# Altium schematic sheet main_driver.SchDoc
size A3
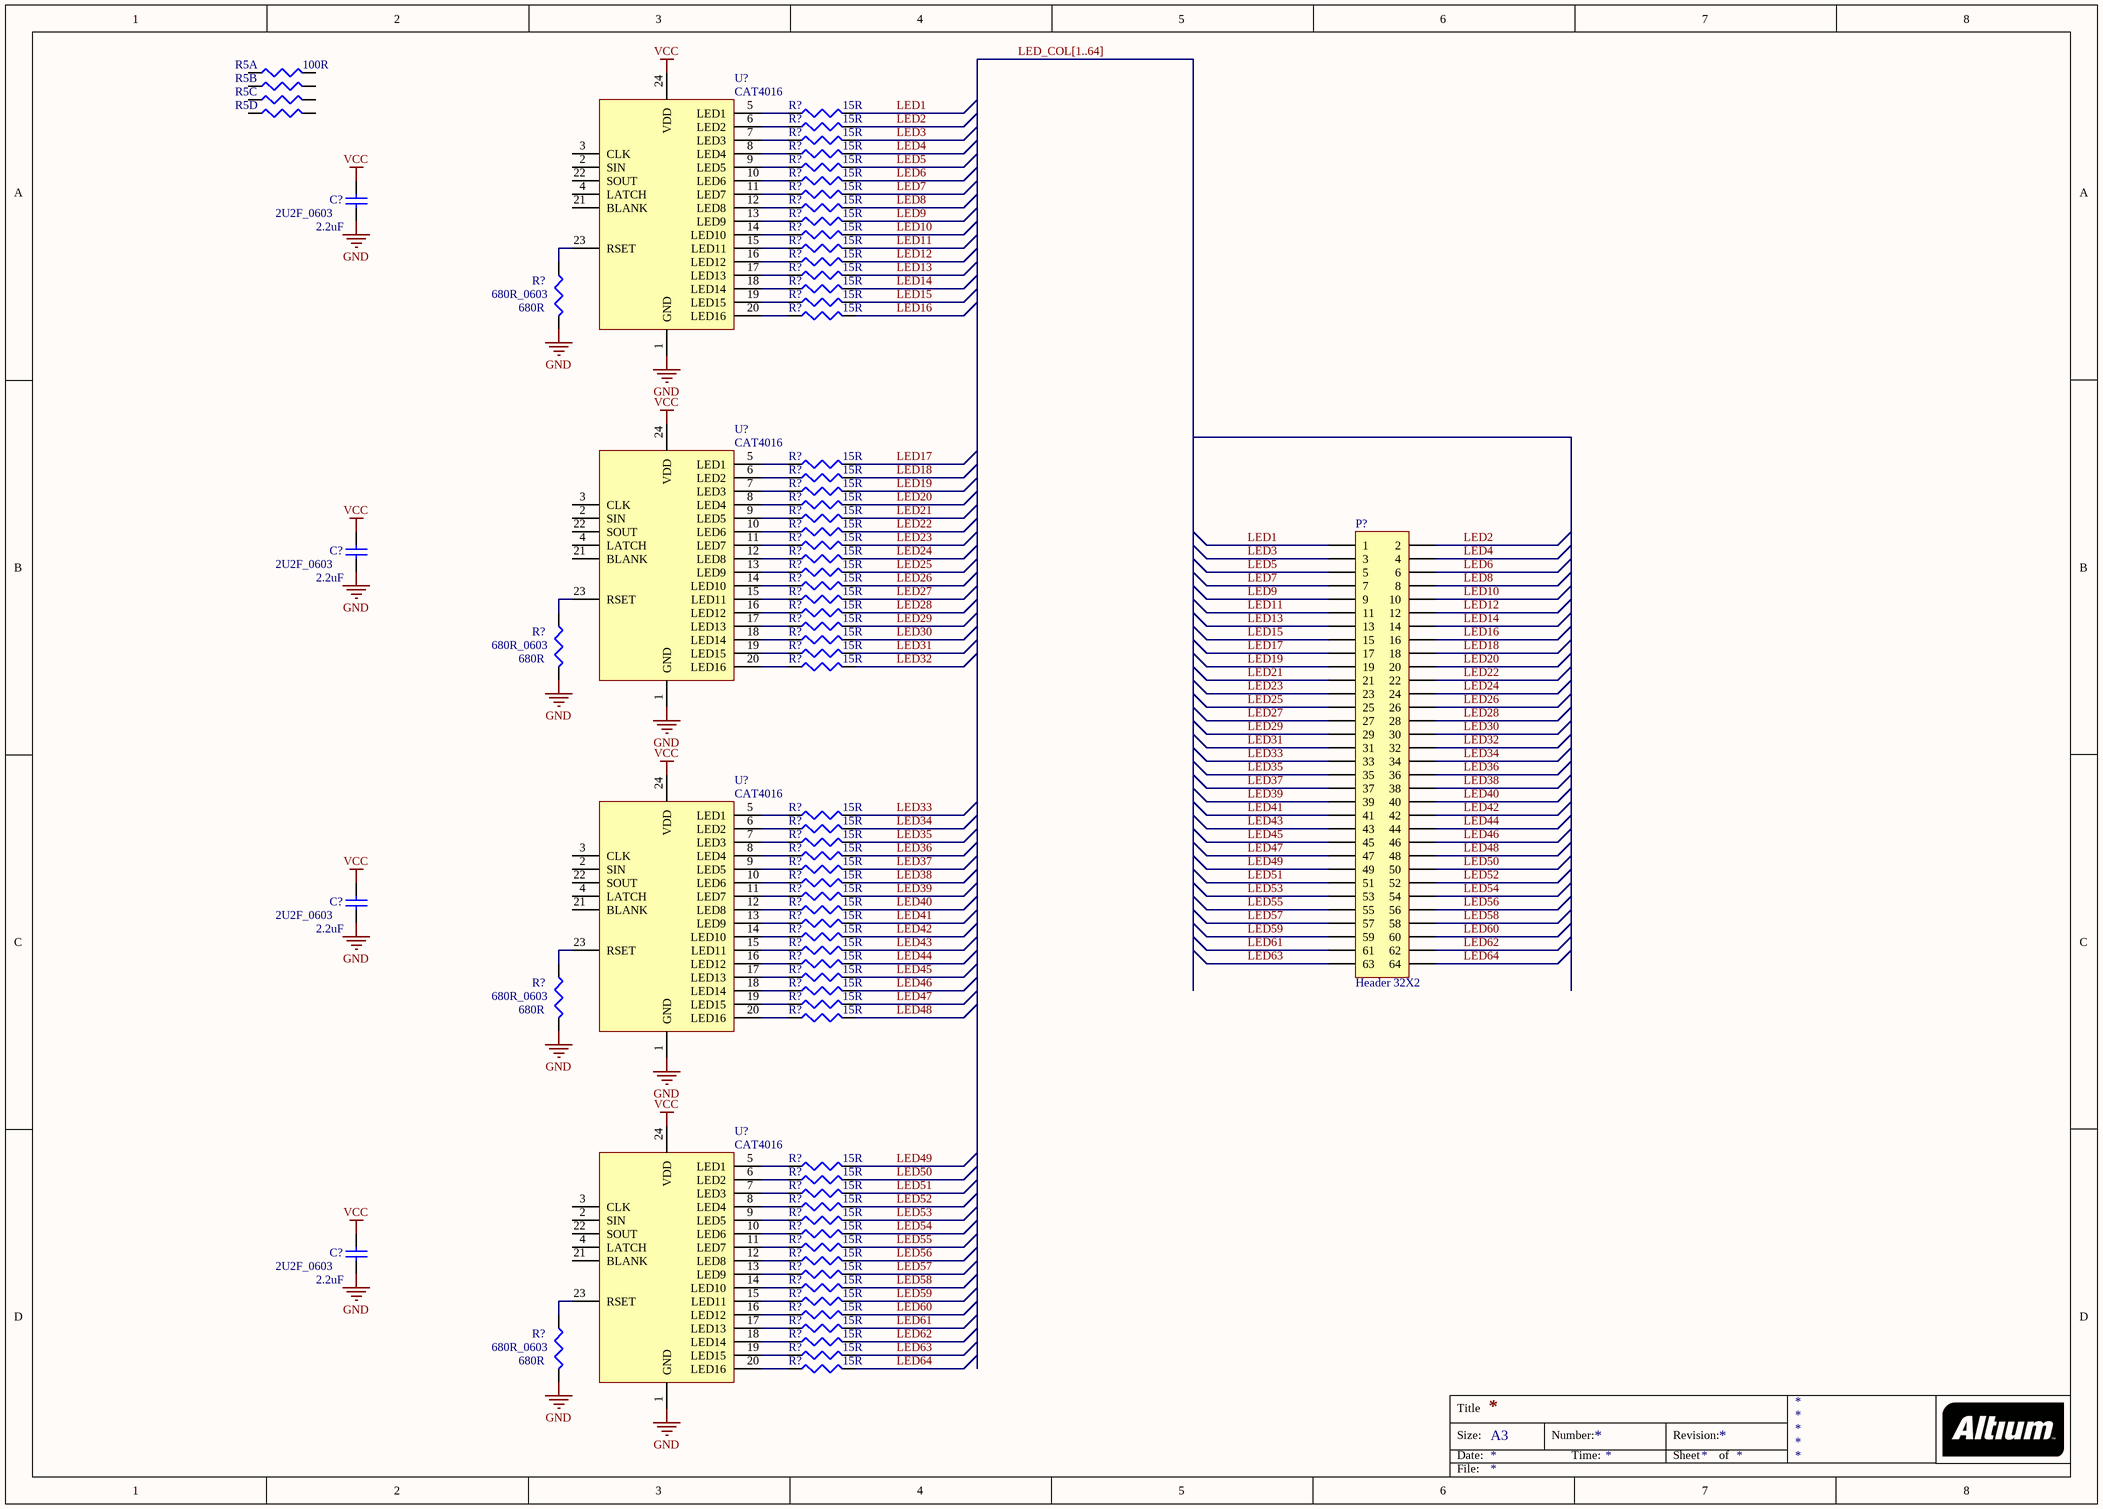
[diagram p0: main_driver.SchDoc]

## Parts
(Parts that share a designator on the sheet are numbered #1, #2 ... from top to bottom, then left to right.)
C?#1  2U2F_0603  value 2.2uF  [C0603]
C?#2  2U2F_0603  value 2.2uF  [C0603]
C?#3  2U2F_0603  value 2.2uF  [C0603]
C?#4  2U2F_0603  value 2.2uF  [C0603]
P?  Header 32X2  [HDR2X32_1MM]
R5  value 100R  [BCN16]  (hidden comment: Res_Array_BCN16)  (parts A,B,C,D of 4)
R?#1  value 15R  [R1206]  (hidden comment: 15R_1206)
R?#2  value 15R  [R1206]  (hidden comment: 15R_1206)
R?#3  value 15R  [R1206]  (hidden comment: 15R_1206)
R?#4  value 15R  [R1206]  (hidden comment: 15R_1206)
R?#5  value 15R  [R1206]  (hidden comment: 15R_1206)
R?#6  value 15R  [R1206]  (hidden comment: 15R_1206)
R?#7  value 15R  [R1206]  (hidden comment: 15R_1206)
R?#8  value 15R  [R1206]  (hidden comment: 15R_1206)
R?#9  value 15R  [R1206]  (hidden comment: 15R_1206)
R?#10  value 15R  [R1206]  (hidden comment: 15R_1206)
R?#11  value 15R  [R1206]  (hidden comment: 15R_1206)
R?#12  value 15R  [R1206]  (hidden comment: 15R_1206)
R?#13  value 15R  [R1206]  (hidden comment: 15R_1206)
R?#14  680R_0603  value 680R  [R0603]
R?#15  value 15R  [R1206]  (hidden comment: 15R_1206)
R?#16  value 15R  [R1206]  (hidden comment: 15R_1206)
R?#17  value 15R  [R1206]  (hidden comment: 15R_1206)
R?#18  value 15R  [R1206]  (hidden comment: 15R_1206)
R?#19  value 15R  [R1206]  (hidden comment: 15R_1206)
R?#20  value 15R  [R1206]  (hidden comment: 15R_1206)
R?#21  value 15R  [R1206]  (hidden comment: 15R_1206)
R?#22  value 15R  [R1206]  (hidden comment: 15R_1206)
R?#23  value 15R  [R1206]  (hidden comment: 15R_1206)
R?#24  value 15R  [R1206]  (hidden comment: 15R_1206)
R?#25  value 15R  [R1206]  (hidden comment: 15R_1206)
R?#26  value 15R  [R1206]  (hidden comment: 15R_1206)
R?#27  value 15R  [R1206]  (hidden comment: 15R_1206)
R?#28  value 15R  [R1206]  (hidden comment: 15R_1206)
R?#29  value 15R  [R1206]  (hidden comment: 15R_1206)
R?#30  value 15R  [R1206]  (hidden comment: 15R_1206)
R?#31  680R_0603  value 680R  [R0603]
R?#32  value 15R  [R1206]  (hidden comment: 15R_1206)
R?#33  value 15R  [R1206]  (hidden comment: 15R_1206)
R?#34  value 15R  [R1206]  (hidden comment: 15R_1206)
R?#35  value 15R  [R1206]  (hidden comment: 15R_1206)
R?#36  value 15R  [R1206]  (hidden comment: 15R_1206)
R?#37  value 15R  [R1206]  (hidden comment: 15R_1206)
R?#38  value 15R  [R1206]  (hidden comment: 15R_1206)
R?#39  value 15R  [R1206]  (hidden comment: 15R_1206)
R?#40  value 15R  [R1206]  (hidden comment: 15R_1206)
R?#41  value 15R  [R1206]  (hidden comment: 15R_1206)
R?#42  value 15R  [R1206]  (hidden comment: 15R_1206)
R?#43  value 15R  [R1206]  (hidden comment: 15R_1206)
R?#44  value 15R  [R1206]  (hidden comment: 15R_1206)
R?#45  value 15R  [R1206]  (hidden comment: 15R_1206)
R?#46  value 15R  [R1206]  (hidden comment: 15R_1206)
R?#47  value 15R  [R1206]  (hidden comment: 15R_1206)
R?#48  680R_0603  value 680R  [R0603]
R?#49  value 15R  [R1206]  (hidden comment: 15R_1206)
R?#50  value 15R  [R1206]  (hidden comment: 15R_1206)
R?#51  value 15R  [R1206]  (hidden comment: 15R_1206)
R?#52  value 15R  [R1206]  (hidden comment: 15R_1206)
R?#53  value 15R  [R1206]  (hidden comment: 15R_1206)
R?#54  value 15R  [R1206]  (hidden comment: 15R_1206)
R?#55  value 15R  [R1206]  (hidden comment: 15R_1206)
R?#56  value 15R  [R1206]  (hidden comment: 15R_1206)
R?#57  value 15R  [R1206]  (hidden comment: 15R_1206)
R?#58  value 15R  [R1206]  (hidden comment: 15R_1206)
R?#59  value 15R  [R1206]  (hidden comment: 15R_1206)
R?#60  value 15R  [R1206]  (hidden comment: 15R_1206)
R?#61  value 15R  [R1206]  (hidden comment: 15R_1206)
R?#62  value 15R  [R1206]  (hidden comment: 15R_1206)
R?#63  value 15R  [R1206]  (hidden comment: 15R_1206)
R?#64  value 15R  [R1206]  (hidden comment: 15R_1206)
R?#65  680R_0603  value 680R  [R0603]
R?#66  value 15R  [R1206]  (hidden comment: 15R_1206)
R?#67  value 15R  [R1206]  (hidden comment: 15R_1206)
R?#68  value 15R  [R1206]  (hidden comment: 15R_1206)
U?#1  CAT4016  [SOIC-24_W]
U?#2  CAT4016  [SOIC-24_W]
U?#3  CAT4016  [SOIC-24_W]
U?#4  CAT4016  [SOIC-24_W]

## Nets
GND: C?#1.1 C?#2.1 C?#3.1 C?#4.1 R?#14.2 R?#31.2 R?#48.2 R?#65.2 U?#1.1(GND) U?#2.1(GND) U?#3.1(GND) U?#4.1(GND)
VCC: C?#1.2 C?#2.2 C?#3.2 C?#4.2 U?#1.24(VDD) U?#2.24(VDD) U?#3.24(VDD) U?#4.24(VDD)
LED1: P?.1 R?#1.2
LED2: P?.2 R?#2.2
LED3: P?.3 R?#3.2
LED4: P?.4 R?#4.2
LED5: P?.5 R?#5.2
LED6: P?.6 R?#6.2
LED7: P?.7 R?#7.2
LED8: P?.8 R?#8.2
LED9: P?.9 R?#9.2
LED10: P?.10 R?#10.2
LED11: P?.11 R?#11.2
LED12: P?.12 R?#12.2
LED13: P?.13 R?#13.2
LED14: P?.14 R?#15.2
LED15: P?.15 R?#16.2
LED16: P?.16 R?#17.2
LED17: P?.17 R?#18.2
LED18: P?.18 R?#19.2
LED19: P?.19 R?#20.2
LED20: P?.20 R?#21.2
LED21: P?.21 R?#22.2
LED22: P?.22 R?#23.2
LED23: P?.23 R?#24.2
LED24: P?.24 R?#25.2
LED25: P?.25 R?#26.2
LED26: P?.26 R?#27.2
LED27: P?.27 R?#28.2
LED28: P?.28 R?#29.2
LED29: P?.29 R?#30.2
LED30: P?.30 R?#32.2
LED31: P?.31 R?#33.2
LED32: P?.32 R?#34.2
LED33: P?.33 R?#35.2
LED34: P?.34 R?#36.2
LED35: P?.35 R?#37.2
LED36: P?.36 R?#38.2
LED37: P?.37 R?#39.2
LED38: P?.38 R?#40.2
LED39: P?.39 R?#41.2
LED40: P?.40 R?#42.2
LED41: P?.41 R?#43.2
LED42: P?.42 R?#44.2
LED43: P?.43 R?#45.2
LED44: P?.44 R?#46.2
LED45: P?.45 R?#47.2
LED46: P?.46 R?#49.2
LED47: P?.47 R?#50.2
LED48: P?.48 R?#51.2
LED49: P?.49 R?#52.2
LED50: P?.50 R?#53.2
LED51: P?.51 R?#54.2
LED52: P?.52 R?#55.2
LED53: P?.53 R?#56.2
LED54: P?.54 R?#57.2
LED55: P?.55 R?#58.2
LED56: P?.56 R?#59.2
LED57: P?.57 R?#60.2
LED58: P?.58 R?#61.2
LED59: P?.59 R?#62.2
LED60: P?.60 R?#63.2
LED61: P?.61 R?#64.2
LED62: P?.62 R?#66.2
LED63: P?.63 R?#67.2
LED64: P?.64 R?#68.2
NetR?#1_1: R?#1.1 U?#1.5(LED1)
NetR?#2_1: R?#2.1 U?#1.6(LED2)
NetR?#3_1: R?#3.1 U?#1.7(LED3)
NetR?#4_1: R?#4.1 U?#1.8(LED4)
NetR?#5_1: R?#5.1 U?#1.9(LED5)
NetR?#6_1: R?#6.1 U?#1.10(LED6)
NetR?#7_1: R?#7.1 U?#1.11(LED7)
NetR?#8_1: R?#8.1 U?#1.12(LED8)
NetR?#9_1: R?#9.1 U?#1.13(LED9)
NetR?#10_1: R?#10.1 U?#1.14(LED10)
NetR?#11_1: R?#11.1 U?#1.15(LED11)
NetR?#12_1: R?#12.1 U?#1.16(LED12)
NetR?#13_1: R?#13.1 U?#1.17(LED13)
NetR?#14_1: R?#14.1 U?#1.23(RSET)
NetR?#15_1: R?#15.1 U?#1.18(LED14)
NetR?#16_1: R?#16.1 U?#1.19(LED15)
NetR?#17_1: R?#17.1 U?#1.20(LED16)
NetR?#18_1: R?#18.1 U?#2.5(LED1)
NetR?#19_1: R?#19.1 U?#2.6(LED2)
NetR?#20_1: R?#20.1 U?#2.7(LED3)
NetR?#21_1: R?#21.1 U?#2.8(LED4)
NetR?#22_1: R?#22.1 U?#2.9(LED5)
NetR?#23_1: R?#23.1 U?#2.10(LED6)
NetR?#24_1: R?#24.1 U?#2.11(LED7)
NetR?#25_1: R?#25.1 U?#2.12(LED8)
NetR?#26_1: R?#26.1 U?#2.13(LED9)
NetR?#27_1: R?#27.1 U?#2.14(LED10)
NetR?#28_1: R?#28.1 U?#2.15(LED11)
NetR?#29_1: R?#29.1 U?#2.16(LED12)
NetR?#30_1: R?#30.1 U?#2.17(LED13)
NetR?#31_1: R?#31.1 U?#2.23(RSET)
NetR?#32_1: R?#32.1 U?#2.18(LED14)
NetR?#33_1: R?#33.1 U?#2.19(LED15)
NetR?#34_1: R?#34.1 U?#2.20(LED16)
NetR?#35_1: R?#35.1 U?#3.5(LED1)
NetR?#36_1: R?#36.1 U?#3.6(LED2)
NetR?#37_1: R?#37.1 U?#3.7(LED3)
NetR?#38_1: R?#38.1 U?#3.8(LED4)
NetR?#39_1: R?#39.1 U?#3.9(LED5)
NetR?#40_1: R?#40.1 U?#3.10(LED6)
NetR?#41_1: R?#41.1 U?#3.11(LED7)
NetR?#42_1: R?#42.1 U?#3.12(LED8)
NetR?#43_1: R?#43.1 U?#3.13(LED9)
NetR?#44_1: R?#44.1 U?#3.14(LED10)
NetR?#45_1: R?#45.1 U?#3.15(LED11)
NetR?#46_1: R?#46.1 U?#3.16(LED12)
NetR?#47_1: R?#47.1 U?#3.17(LED13)
NetR?#48_1: R?#48.1 U?#3.23(RSET)
NetR?#49_1: R?#49.1 U?#3.18(LED14)
NetR?#50_1: R?#50.1 U?#3.19(LED15)
NetR?#51_1: R?#51.1 U?#3.20(LED16)
NetR?#52_1: R?#52.1 U?#4.5(LED1)
NetR?#53_1: R?#53.1 U?#4.6(LED2)
NetR?#54_1: R?#54.1 U?#4.7(LED3)
NetR?#55_1: R?#55.1 U?#4.8(LED4)
NetR?#56_1: R?#56.1 U?#4.9(LED5)
NetR?#57_1: R?#57.1 U?#4.10(LED6)
NetR?#58_1: R?#58.1 U?#4.11(LED7)
NetR?#59_1: R?#59.1 U?#4.12(LED8)
NetR?#60_1: R?#60.1 U?#4.13(LED9)
NetR?#61_1: R?#61.1 U?#4.14(LED10)
NetR?#62_1: R?#62.1 U?#4.15(LED11)
NetR?#63_1: R?#63.1 U?#4.16(LED12)
NetR?#64_1: R?#64.1 U?#4.17(LED13)
NetR?#65_1: R?#65.1 U?#4.23(RSET)
NetR?#66_1: R?#66.1 U?#4.18(LED14)
NetR?#67_1: R?#67.1 U?#4.19(LED15)
NetR?#68_1: R?#68.1 U?#4.20(LED16)

Not connected (* = marked no-connect by the designer): R5 1 2(1) 3(1) 4(1) 5(2) 6(2) 7(2) 8(2); U?#1 2(SIN) 3(CLK) 4(LATCH) 21(BLANK) 22(SOUT); U?#2 2(SIN) 3(CLK) 4(LATCH) 21(BLANK) 22(SOUT); U?#3 2(SIN) 3(CLK) 4(LATCH) 21(BLANK) 22(SOUT); U?#4 2(SIN) 3(CLK) 4(LATCH) 21(BLANK) 22(SOUT)

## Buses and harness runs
bus LED_COL[1..64]

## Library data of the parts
C?#1-C?#4 = Cap Semi: Capacitor (Semiconductor SIM Model)
P? = Header 32X2: Header, 32-Pin, Dual row
R5 = Res_Array_BCN16: Resistor
R?#1-R?#68 = Res3: Resistor
U?#1-U?#4 = CAT4016: 16channel LED driver - constant current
